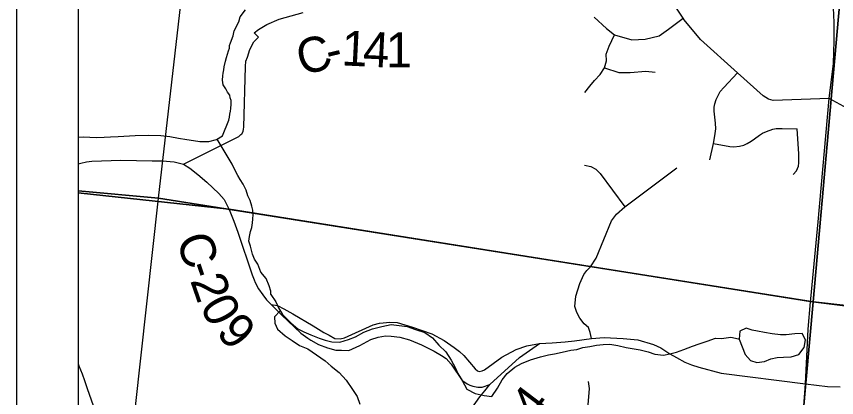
# Model space of a CAD drawing. Extents: x 0 to 34, y -2 to 22.
# Drawn here: x 2 to 3.329, y 17.805 to 18.423 of the extents above; entities that cross this region are included whole.
import ezdxf

# ---------------------------------------------------------------- set-up
doc = ezdxf.new("R2010")
doc.units = 0
for name, color, linetype in [('Default', 7, 'Continuous'), ('GM_X_County_Road', 7, 'Continuous'), ('GM_X_County_Road_Text', 7, 'Continuous'), ('GM_X_Minor_Lake', 7, 'Continuous'), ('GM_X_Minor_River', 7, 'Continuous'), ('GM_X_Rail_Line', 7, 'Continuous'), ('GM_X_Section', 7, 'Continuous'), ('GM_X_Township_Road', 7, 'Continuous'), ('SH_Cut_Line', 7, 'Continuous'), ('SH_Data', 7, 'Continuous')]:
    doc.layers.add(name, color=color, linetype=linetype)

msp = doc.modelspace()

# ---------------------------------------------------------------- linework, layer by layer
at = {"layer": 'Default'}
for points in [[(2.1, 19.1108), (2.1, 18.1402), (2.2302, 18.1283), (2.3398, 19.083)], [(2.1, 18.1402), (2.1, 17.017), (2.1074, 17.0167), (2.2302, 18.1283)]]:
    msp.add_lwpolyline(points, close=True, dxfattribs=at)
at = {"layer": 'GM_X_County_Road'}
for points in [[(3.2876, 17.9648), (3.2993, 18.0896), (3.3169, 18.29), (3.3244, 18.3467), (3.3252, 18.3831), (3.3254, 18.4128), (3.3239, 18.4367), (3.3234, 18.4405), (3.3209, 18.4585), (3.3149, 18.4849), (3.3131, 18.4986), (3.3129, 18.5153), (3.3143, 18.5465), (3.3238, 18.6498), (3.324, 18.6527)], [(3.3169, 18.29), (3.2265, 18.2864), (3.219, 18.2885), (3.2101, 18.2938), (3.1687, 18.3312), (3.1088, 18.3855), (3.0822, 18.4172), (3.0803, 18.42), (3.0392, 18.4831), (3.0325, 18.486), (3.0247, 18.4912), (3.0177, 18.4979), (2.9894, 18.5364), (2.9873, 18.5407)], [(2.2709, 18.1831), (2.3606, 18.2283), (2.3637, 18.2311), (2.3652, 18.2325), (2.3675, 18.2363), (2.3682, 18.2399), (2.3688, 18.2431), (2.3712, 18.3418), (2.3719, 18.3505), (2.3746, 18.3566), (2.3783, 18.369), (2.385, 18.3814), (2.3925, 18.3893), (2.3853, 18.3962), (2.3922, 18.4018), (2.406, 18.4098), (2.4259, 18.4185), (2.4645, 18.4294)], [(3.4549, 18.1718), (3.4521, 18.1749), (3.4075, 18.2217), (3.3688, 18.2666), (3.3673, 18.2678), (3.3628, 18.2699), (3.3411, 18.2766), (3.3169, 18.29)], [(2.1, 18.1837), (2.1043, 18.1851), (2.1136, 18.1869), (2.1225, 18.1881), (2.1694, 18.1899), (2.2198, 18.1889), (2.2367, 18.1889), (2.243, 18.1881), (2.2494, 18.1876), (2.2557, 18.1868), (2.2709, 18.1831), (2.281, 18.177), (2.2939, 18.1665), (2.3088, 18.1538), (2.3278, 18.1358), (2.3367, 18.126), (2.3449, 18.1096), (2.3521, 18.0909), (2.3588, 18.0728), (2.3821, 18.0037), (2.3851, 17.9958)], [(2.3851, 17.9958), (2.3868, 17.9914), (2.3922, 17.981), (2.3996, 17.9713), (2.4053, 17.9631), (2.4128, 17.9555)], [(3.2513, 17.5609), (3.2719, 17.7328), (3.2788, 17.8269), (3.283, 17.9159), (3.2871, 17.9598), (3.2876, 17.9648)], [(2.4128, 17.9555), (2.4301, 17.9384), (2.461, 17.9092), (2.4725, 17.9012)], [(2.4128, 17.9555), (2.4229, 17.954), (2.4336, 17.9485), (2.4479, 17.9404), (2.4811, 17.9213), (2.4982, 17.9104), (2.5068, 17.9059), (2.516, 17.9005), (2.5249, 17.8998), (2.5318, 17.9015), (2.5784, 17.9229), (2.5884, 17.9255), (2.5941, 17.9261), (2.6052, 17.9269), (2.617, 17.9266), (2.6419, 17.9188), (2.6731, 17.9079), (2.6931, 17.8975), (2.7094, 17.8861), (2.7179, 17.8796), (2.7252, 17.8732), (2.7434, 17.8515), (2.7471, 17.8481), (2.7501, 17.8468), (2.7547, 17.8479), (2.7587, 17.8498), (2.7867, 17.8702), (2.8098, 17.8826), (2.8274, 17.8886), (2.8479, 17.8923)], [(2.4725, 17.9012), (2.4774, 17.8978), (2.4895, 17.8906), (2.5039, 17.8854), (2.5177, 17.8819), (2.5266, 17.8814), (2.5388, 17.8812), (2.5565, 17.8892), (2.5744, 17.8988), (2.5865, 17.903), (2.5982, 17.9047), (2.6071, 17.9046), (2.6216, 17.9025), (2.6371, 17.8984), (2.6567, 17.8905), (2.6772, 17.88), (2.6888, 17.8732), (2.6963, 17.8679), (2.7048, 17.8587), (2.7225, 17.8327), (2.7267, 17.8296), (2.7303, 17.8272), (2.7348, 17.8248), (2.7398, 17.8232), (2.7478, 17.8217), (2.7549, 17.8218), (2.7671, 17.8259)], [(2.7671, 17.8259), (2.8151, 17.8696), (2.8479, 17.8923), (2.868, 17.8933), (2.8891, 17.8949), (2.9042, 17.8969), (2.9319, 17.9006), (2.9523, 17.9024), (2.9832, 17.9004), (3.0072, 17.8985), (3.0322, 17.8908), (3.0445, 17.8852), (3.059, 17.8756), (3.0697, 17.8695), (3.083, 17.8624), (3.0939, 17.8577), (3.1061, 17.8539), (3.1421, 17.8442), (3.2788, 17.8269), (3.3142, 17.8225), (3.3348, 17.8222)], [(2.6848, 17.3574), (2.7003, 17.4866), (2.7102, 17.5633), (2.7153, 17.6344), (2.7205, 17.6753), (2.7287, 17.7562), (2.7291, 17.7626), (2.7323, 17.7756), (2.7379, 17.7878), (2.7511, 17.8061), (2.7591, 17.8155), (2.7671, 17.8259)]]:
    msp.add_lwpolyline(points, dxfattribs=at)
at = {"layer": 'GM_X_Minor_Lake'}
for points in [[(3.2012, 17.9123), (3.1924, 17.914), (3.1828, 17.9174), (3.1721, 17.9123), (3.1711, 17.8996)], [(3.1711, 17.8996), (3.1762, 17.8871), (3.1808, 17.8748), (3.1897, 17.8647), (3.1998, 17.8618), (3.2124, 17.8634), (3.2228, 17.8677), (3.2327, 17.8697), (3.243, 17.8705), (3.2555, 17.871), (3.2681, 17.8748), (3.2768, 17.886), (3.2786, 17.8984), (3.2736, 17.9085), (3.2614, 17.908), (3.2477, 17.9065), (3.2382, 17.9067), (3.2246, 17.9082), (3.2125, 17.9101), (3.2012, 17.9123)]]:
    msp.add_lwpolyline(points, dxfattribs=at)
at = {"layer": 'GM_X_Minor_River'}
for points in [[(2.334, 18.2294), (2.3441, 18.2548), (2.3454, 18.2593), (2.3459, 18.2642), (2.3469, 18.2692), (2.3474, 18.2737), (2.348, 18.2805), (2.3479, 18.2866), (2.3465, 18.2908), (2.3459, 18.295), (2.3419, 18.3001), (2.3394, 18.3055), (2.3351, 18.3118), (2.3342, 18.3194), (2.3348, 18.3266), (2.335, 18.3308), (2.3359, 18.3361), (2.3368, 18.341), (2.339, 18.3504), (2.3404, 18.3564), (2.3438, 18.3669), (2.3451, 18.3715), (2.3456, 18.3756), (2.3469, 18.3798), (2.3511, 18.3914), (2.3529, 18.3997), (2.3602, 18.4143), (2.3628, 18.4222), (2.3711, 18.4333)], [(2.1, 18.2273), (2.1086, 18.2274), (2.1192, 18.2271), (2.1294, 18.2265), (2.1423, 18.2269), (2.1526, 18.2274), (2.1651, 18.2279), (2.1925, 18.2295), (2.2138, 18.2305), (2.2339, 18.23), (2.2486, 18.2281), (2.2626, 18.2255), (2.2762, 18.2232), (2.2872, 18.2218), (2.2974, 18.22), (2.3118, 18.22), (2.3244, 18.2231), (2.334, 18.2294)], [(2.3913, 18.0212), (2.3857, 18.0293), (2.3828, 18.0373), (2.3792, 18.0503), (2.3767, 18.0583), (2.3776, 18.0659), (2.3792, 18.0739), (2.3816, 18.0807), (2.3825, 18.0882), (2.3834, 18.0939), (2.3839, 18.1019), (2.3833, 18.1088), (2.3815, 18.1152), (2.3786, 18.1244), (2.3749, 18.1321), (2.3721, 18.1409), (2.3677, 18.1508), (2.3624, 18.1582), (2.3591, 18.1651), (2.3532, 18.1754), (2.3499, 18.1831), (2.3251, 18.2236)], [(2.4121, 17.9718), (2.4122, 17.9771), (2.4097, 17.9859), (2.4046, 17.9981), (2.396, 18.0082), (2.3913, 18.0212)], [(2.4121, 17.9718), (2.4202, 17.9598), (2.4249, 17.9502), (2.4314, 17.9394), (2.4448, 17.9262), (2.4559, 17.9164), (2.466, 17.9112), (2.4769, 17.9064), (2.4904, 17.9011), (2.5006, 17.8978), (2.5111, 17.8949), (2.5244, 17.8946), (2.5382, 17.8988), (2.5497, 17.9034), (2.5632, 17.9111), (2.5773, 17.916), (2.5922, 17.9202), (2.6075, 17.9232), (2.6204, 17.9218), (2.6332, 17.9199), (2.6468, 17.915), (2.6618, 17.9101), (2.6741, 17.9018), (2.6845, 17.8898), (2.696, 17.8792), (2.7047, 17.8654), (2.7109, 17.8534), (2.7155, 17.8438), (2.7225, 17.8326), (2.7297, 17.8184), (2.7436, 17.8116), (2.7579, 17.8082), (2.7704, 17.8067), (2.7798, 17.8202), (2.7874, 17.8333), (2.7952, 17.8437), (2.8077, 17.854), (2.8184, 17.8602), (2.833, 17.8659), (2.8495, 17.8708), (2.8624, 17.8743), (2.872, 17.8756), (2.8846, 17.8783), (2.8987, 17.8814), (2.9082, 17.883), (2.9181, 17.8858), (2.9292, 17.8878), (2.9399, 17.8895), (2.9509, 17.8911), (2.9616, 17.8916), (2.9748, 17.889), (2.988, 17.886), (2.9978, 17.8842), (3.0107, 17.882), (3.0239, 17.879), (3.0348, 17.8749), (3.0484, 17.8735), (3.0591, 17.8755), (3.0698, 17.8786), (3.0816, 17.8825), (3.0955, 17.8882), (3.1066, 17.8921), (3.1192, 17.8964), (3.133, 17.901), (3.1425, 17.9007), (3.1577, 17.903), (3.1701, 17.9), (3.1713, 17.8995)], [(2.4276, 17.9457), (2.4184, 17.9356), (2.4186, 17.9257), (2.4232, 17.9157), (2.4355, 17.9051), (2.4467, 17.8973), (2.4586, 17.8894), (2.4721, 17.8837), (2.4863, 17.8742), (2.5005, 17.8644), (2.5101, 17.8558), (2.5232, 17.8456), (2.5342, 17.8332), (2.5449, 17.8177), (2.5522, 17.8065), (2.5564, 17.7939)], [(2.1, 17.8594), (2.1014, 17.8562), (2.1068, 17.8435), (2.1103, 17.8324), (2.1145, 17.8194), (2.1244, 17.7918)]]:
    msp.add_lwpolyline(points, dxfattribs=at)
at = {"layer": 'GM_X_Rail_Line'}
for points in [[(7.5809, 20.9), (2.1, 20.9), (2.1, 18.1368), (2.3446, 18.1102), (2.9298, 18.0171), (3.2869, 17.9604), (3.6832, 17.9108)], [(3.6832, 17.9108), (3.2869, 17.9604), (2.9298, 18.0171), (2.3446, 18.1102), (2.1, 18.1368), (2.1, 16.3648), (2.1342, 16.3571), (2.2291, 16.3515), (2.5217, 16.3621), (2.6166, 16.3275), (2.9069, 16.2111), (3.202, 16.0321), (3.297, 15.9555), (3.6339, 15.5717)]]:
    msp.add_lwpolyline(points, dxfattribs=at)
at = {"layer": 'GM_X_Section'}
for points in [[(2.3398, 19.083), (3.3818, 18.9832), (3.2914, 17.96), (2.2302, 18.1283)], [(4.3356, 18.8839), (4.2197, 17.8557), (3.2914, 17.96), (3.3818, 18.9832)], [(3.2914, 17.96), (3.2017, 16.9647), (2.1074, 17.0167), (2.2302, 18.1283)], [(4.2197, 17.8557), (4.1192, 16.9159), (3.2017, 16.9647), (3.2914, 17.96)]]:
    msp.add_lwpolyline(points, close=True, dxfattribs=at)
at = {"layer": 'GM_X_Township_Road'}
for points in [[(2.9365, 18.4214), (2.9565, 18.4035), (2.969, 18.3931), (2.9973, 18.3848), (3.019, 18.3859), (3.0418, 18.3914), (3.057, 18.4021), (3.0803, 18.42)], [(2.9213, 18.2996), (2.9293, 18.3096), (2.9369, 18.3189), (2.9458, 18.3286), (2.9528, 18.3396), (2.9565, 18.3507), (2.9559, 18.3617), (2.9607, 18.3748), (2.969, 18.3931)], [(2.9528, 18.3396), (2.9762, 18.3317), (2.9945, 18.3317), (3.0201, 18.3338), (3.0352, 18.3324)], [(3.1239, 18.1901), (3.1295, 18.2169), (3.1321, 18.2292), (3.1335, 18.2406), (3.1328, 18.2495), (3.1317, 18.2596), (3.131, 18.2694), (3.131, 18.2756), (3.1319, 18.281), (3.1342, 18.2879), (3.1371, 18.2948), (3.1406, 18.3011), (3.1464, 18.3073), (3.1687, 18.3312)], [(3.1295, 18.2169), (3.1562, 18.212), (3.1625, 18.2114), (3.1716, 18.2124), (3.1786, 18.2141), (3.1844, 18.2167), (3.1906, 18.2203), (3.196, 18.2242), (3.2041, 18.2304), (3.2089, 18.2336), (3.2155, 18.2364), (3.2258, 18.2398), (3.2314, 18.2409), (3.2407, 18.241), (3.2651, 18.2405)], [(3.2587, 18.1667), (3.2642, 18.1723), (3.2672, 18.1798), (3.2682, 18.1853), (3.2681, 18.2), (3.2651, 18.2405)], [(2.9206, 18.1818), (2.9309, 18.1797), (2.939, 18.1754), (2.9459, 18.1681), (2.9861, 18.114)], [(2.9301, 18.0166), (2.9393, 18.0306), (2.9642, 18.0916), (2.9724, 18.1023), (2.9861, 18.114), (3.0701, 18.1771)], [(2.9319, 17.9006), (2.9297, 17.9103), (2.9271, 17.9183), (2.9202, 17.9246), (2.9131, 17.9334), (2.9082, 17.9427), (2.9049, 17.9525), (2.9065, 17.969), (2.9131, 17.9898), (2.9197, 18.0045), (2.9246, 18.0111), (2.9301, 18.0166)], [(3.0341, 17.7077), (3.0308, 17.7095), (3.0026, 17.7134), (2.9738, 17.7173), (2.9123, 17.7269), (2.9168, 17.7425), (2.9255, 17.7799), (2.9285, 17.8195), (2.9273, 17.8309)]]:
    msp.add_lwpolyline(points, dxfattribs=at)
at = {"layer": 'SH_Cut_Line'}
msp.add_lwpolyline([(8.9, 20.9), (2.1, 20.9), (2.1, 16.3648), (2.1342, 16.3571), (2.2291, 16.3515), (2.5217, 16.3621), (2.6166, 16.3275), (2.9069, 16.2111), (3.202, 16.0321), (3.297, 15.9555), (3.6339, 15.5717)], dxfattribs=at)
at = {"layer": 'SH_Data'}
for p, q in [((2, 21), (2, 14)), ((2.1, 20.9), (2.1, 14.1))]:
    msp.add_line(p, q, dxfattribs=at)

# ---------------------------------------------------------------- texts
at = {"layer": 'GM_X_County_Road_Text'}
for s, rotation, p in [('1', 357.1679, (2.5259, 18.3436)), ('4', 357.1575, (2.5608, 18.3419)), ('1', 0.1017, (2.599, 18.3401)), ('C', 15.2447, (2.4628, 18.3264)), ('-', 13.4238, (2.5074, 18.3386)), ('C', 289.0283, (2.2583, 18.0611)), ('-', 289.045, (2.2735, 18.017)), ('2', 289.1904, (2.2812, 17.9948)), ('0', 297.8054, (2.2964, 17.9532)), ('9', 312.5869, (2.3219, 17.9092)), ('4', 52.8829, (2.8422, 17.7618))]:
    msp.add_text(s, height=0.0568, rotation=rotation, dxfattribs=at).set_placement(p)

doc.saveas('drawing.dxf')
